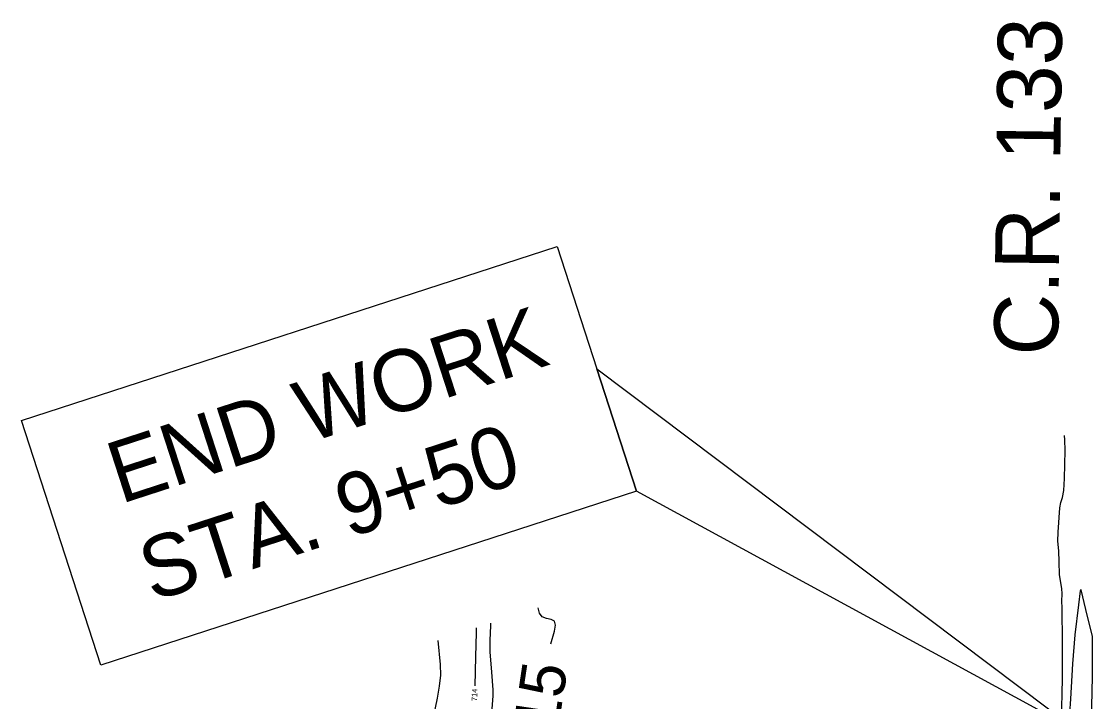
# Model space of a CAD drawing. Extents: x -468563856 to 36492962, y -306094093 to 11899197.
# Drawn here: x 1823596 to 1824380, y 532278 to 532775 of the extents above; entities that cross this region are included whole.
import ezdxf

# ---------------------------------------------------------------- set-up
doc = ezdxf.new("R2010")
doc.units = 0
for name, color, linetype in [('DT_X_Contour_Minor', 7, 'Continuous'), ('Level 19', 7, 'Continuous'), ('Level 40', 7, 'Continuous'), ('SH_Text', 7, 'Continuous')]:
    doc.layers.add(name, color=color, linetype=linetype)

msp = doc.modelspace()

# ---------------------------------------------------------------- linework, layer by layer
at = {"layer": 'DT_X_Contour_Minor'}
for points in [[(1824356.94, 532262.76), (1824357.52, 532294.42), (1824357.49, 532320.66), (1824357.25, 532346.59), (1824357.17, 532350.88), (1824357.27, 532356.77), (1824357.05, 532360.29), (1824355.41, 532370.76), (1824355.28, 532379.92), (1824355.01, 532387.93), (1824354.23, 532395.18), (1824354.53, 532401.54), (1824355.54, 532419.51), (1824356.33, 532423.43), (1824357.59, 532426.89), (1824358.47, 532432.21), (1824359.08, 532440.97), (1824359.45, 532461.22), (1824359.32, 532469.1), (1824359.09, 532472.19)], [(1824370.46, 532358.65), (1824369.19, 532348.49), (1824366.65, 532326.72), (1824364.84, 532305.38), (1824363.4, 532279.71), (1824362.83, 532269.19)], [(1824378.92, 532263.33), (1824379.43, 532296.21), (1824379.6, 532325.42), (1824374.78, 532345.15), (1824371.23, 532359.54), (1824370.98, 532359.58), (1824370.46, 532358.65)], [(1823983.4, 532320.06), (1823986.13, 532329.23), (1823986.82, 532333.58), (1823986.07, 532336.49), (1823983.58, 532337.9), (1823980.22, 532338.66), (1823977.13, 532339.88), (1823975.17, 532342.43), (1823974.04, 532346.27), (1823974.02, 532346.36)], [(1823928.86, 532331.61), (1823928.79, 532328.39), (1823928.27, 532310.44), (1823927.71, 532289.28)], [(1823936.35, 532078.45), (1823936.84, 532109.8), (1823936.37, 532124.67), (1823935.82, 532139.18), (1823936.31, 532154.27), (1823936.92, 532168.73), (1823937.48, 532197.51), (1823938.25, 532225.05), (1823939.35, 532252.79), (1823939.74, 532263.35), (1823941.09, 532282.1), (1823941.07, 532286.43), (1823940.19, 532299.37), (1823939.03, 532314.28), (1823939, 532322.4), (1823939.58, 532333.47), (1823939.57, 532335.1)], [(1823900.62, 532322.38), (1823902.49, 532304.97), (1823902.74, 532297.16), (1823901.79, 532288.98), (1823900.27, 532280.33), (1823897.5, 532267.5), (1823895.93, 532257.35), (1823895.65, 532251.73), (1823895.98, 532246.56), (1823896.09, 532228.14), (1823896.49, 532225.16), (1823897.07, 532223.46), (1823898.5, 532220.8), (1823899.3, 532218.83)]]:
    msp.add_lwpolyline(points, dxfattribs=at)
at = {"layer": 'SH_Text'}
for points in [[(1824046.09, 532431.61), (1823654.22, 532304.38), (1823596.13, 532483.3), (1823988, 532610.52)], [(1824017.05, 532521.06), (1824369.99, 532255.38), (1824046.09, 532431.61)]]:
    msp.add_lwpolyline(points, close=True, dxfattribs=at)

# ---------------------------------------------------------------- texts
at = {"layer": 'Level 19'}
for s, height, rotation, p in [('715', 33, 81.51471, (1823984.84, 532230.87)), ('714', 4, 88.4876, (1823929.41, 532278.02))]:
    msp.add_text(s, height=height, rotation=rotation, dxfattribs=at).set_placement(p)
at = {"layer": 'Level 40'}
msp.add_text('C.R. 133', height=46.8, rotation=89.28304, dxfattribs=at).set_placement((1824354.23, 532530.51))
at = {"layer": 'SH_Text'}
for s, p in [('END WORK', (1823668.64, 532422.08)), ('STA. 9+50', (1823691.84, 532350.63))]:
    msp.add_text(s, height=45.072, rotation=17.9864, dxfattribs=at).set_placement(p)

doc.saveas('drawing.dxf')
